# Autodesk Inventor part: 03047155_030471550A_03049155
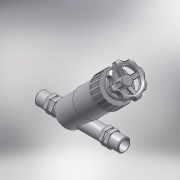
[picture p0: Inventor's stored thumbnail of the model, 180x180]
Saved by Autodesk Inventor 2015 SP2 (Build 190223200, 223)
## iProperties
Created: 2017-05
Part Number: 03047155_030471550A_03049155
Material: Generic
Description: PLASSON ANGLE SEAT VALVE 1.1/2"-1.1/2"
Document SubType Name: Modeling
Designer: KIM
Mass: 184.302 g
Surface Area: 375.869 cm^2
Volume: 184.302 cm^3
Density: 1 g/cm^3
Appearance: Default
Author: KIM
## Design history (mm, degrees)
derived "03047.ipt"
feature "Solid1::03047.ipt"
tag "TaggingFeature1"
body "Solid1"
other parameters: "d1" = 41.91, "d2" = 46, "d3" = 33.528, "d4" = 22, "d5" = 22, "d8" = 2, "d12" = 0, "d15" = 4, "d16" = 0, "d17" = 53.46, "d19" = 170.1, "d20" = 66.42, "d21" = 135 deg, "d22" = 70.47, "d23" = 32.4, "d24" = 76.95, "d25" = 19.44, "d26" = 90 deg, "d27" = 56.7, "d28" = 70 deg, "d29" = 24.3, "d30" = 19.44, "d31" = 24.3, "d32" = 81, "d33" = 56.7, "d34" = 135 deg, "d35" = 2, "d36" = 162, "d40" = 1.8, "d42" = 2, "d43" = 5.4, "d44" = 5.4, "d46" = 0, "d48" = 360 deg, "d50" = 0.9, "d51" = 0.9, "d53" = 360 deg, "d69" = 68.85, "d70" = 5.4, "d71" = 5.4, "d72" = 10.8, "d74" = 0, "d75" = 0.9, "d77" = 360 deg, "d80" = 74.6415, "d81" = 7.2, "d82" = 3.6, "d83" = 29.16, "d84" = 0, "d86" = 360 deg, "d88" = 1.8, "d89" = 6.48, "d90" = 0.9, "R_" = 41.91, "E_" = 46, "l_2" = 22, "d67" = 81, "d68" = 56.7, "d79" = 76.95
